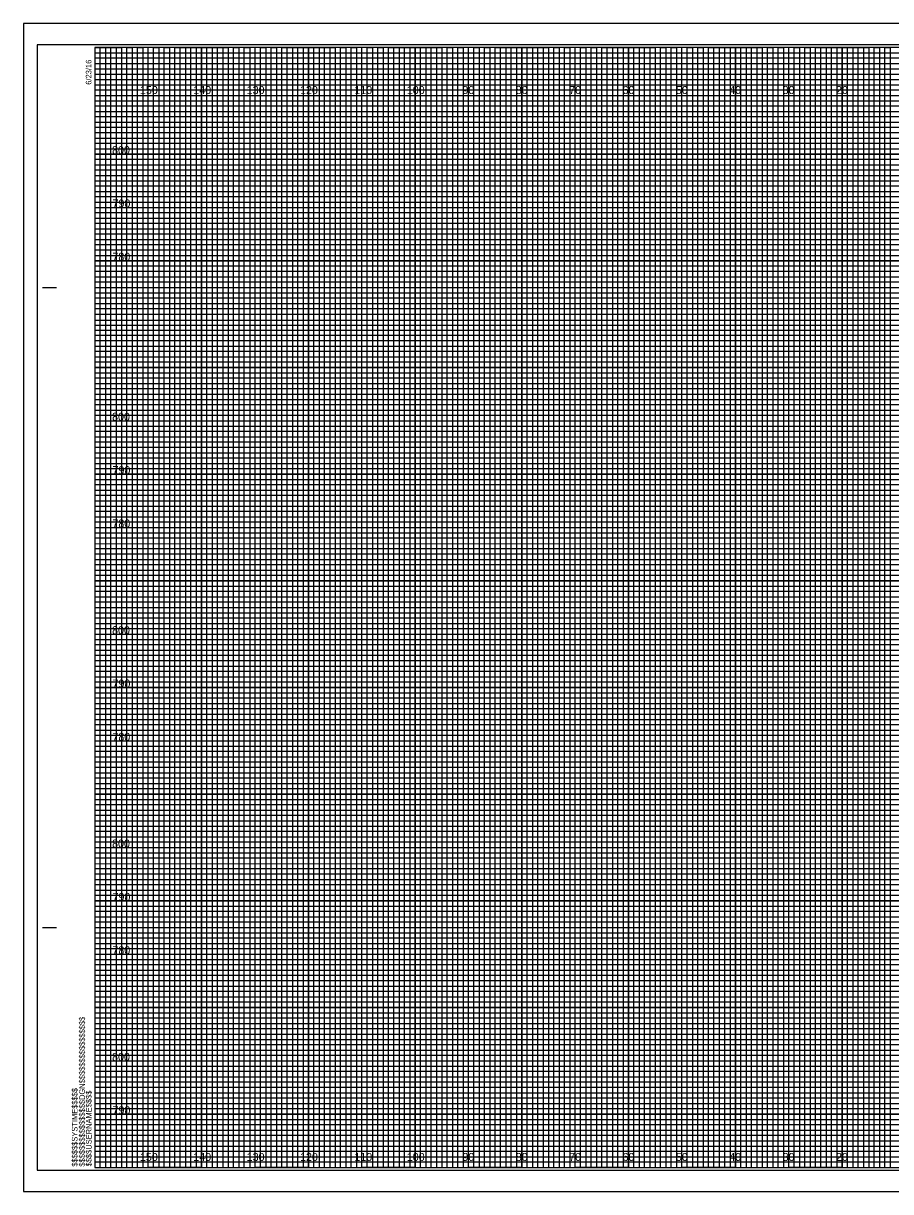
# Model space of a CAD drawing. Extents: x 9987 to 10323, y 9996 to 10214.
# Drawn here: x 9986.6 to 10149.1, y 9995.5 to 10214.5 of the extents above; entities that cross this region are included whole.
import ezdxf

# ---------------------------------------------------------------- set-up
doc = ezdxf.new("R2010")
doc.units = 0
for name, color, linetype in [('Exist Cross Section Cell', 7, 'Continuous'), ('Exist XS Center Line Elevation Label', 7, 'Continuous'), ('Exist XS Ground Line', 7, 'Continuous'), ('Prop CMT Conc Surface', 7, 'Continuous'), ('Prop CMT Concrete Structures', 7, 'Continuous'), ('Prop CMT Pvmt Course 1', 7, 'Continuous'), ('Prop CMT Pvmt Course 1 CG', 7, 'Continuous'), ('Prop CMT Pvmt Course 2', 7, 'Continuous'), ('Prop CMT Pvmt Course 3', 7, 'Continuous'), ('Prop CMT Pvmt Surface', 7, 'Continuous'), ('Prop XS Shear Point Element', 7, 'Continuous')]:
    doc.layers.add(name, color=color, linetype=linetype)

msp = doc.modelspace()

# ---------------------------------------------------------------- linework, layer by layer
at = {"layer": 'Exist XS Center Line Elevation Label'}
for points in [[(10000, 10210), (10005, 10210), (10005, 10000), (10015, 10000), (10015, 10210), (10025, 10210), (10025, 10000), (10035, 10000), (10035, 10210), (10045, 10210), (10045, 10000), (10055, 10000), (10055, 10210), (10065, 10210), (10065, 10000), (10075, 10000), (10075, 10210), (10085, 10210), (10085, 10000), (10095, 10000), (10095, 10210), (10105, 10210), (10105, 10000), (10115, 10000), (10115, 10210), (10125, 10210), (10125, 10000), (10135, 10000), (10135, 10210), (10145, 10210), (10145, 10000), (10155, 10000)], [(10000, 10205), (10275, 10205)], [(10000, 10185), (10320, 10185), (10320, 10195), (10000, 10195)], [(10000, 10165), (10320, 10165), (10320, 10175), (10000, 10175)], [(10000, 10145), (10320, 10145), (10320, 10155), (10000, 10155)], [(10000, 10125), (10320, 10125), (10320, 10135), (10000, 10135)], [(10000, 10105), (10320, 10105), (10320, 10115), (10000, 10115)], [(10000, 10085), (10320, 10085), (10320, 10095), (10000, 10095)], [(10000, 10065), (10320, 10065), (10320, 10075), (10000, 10075)], [(10000, 10045), (10320, 10045), (10320, 10055), (10000, 10055)], [(10000, 10025), (10320, 10025), (10320, 10035), (10000, 10035)], [(10000, 10005), (10320, 10005), (10320, 10015), (10000, 10015)]]:
    msp.add_lwpolyline(points, dxfattribs=at)
at = {"layer": 'Exist XS Ground Line'}
for p, q in [((10010, 10210), (10000, 10210)), ((10010, 10000), (10010, 10210)), ((10030, 10210), (10020, 10210)), ((10020, 10210), (10020, 10000)), ((10030, 10000), (10030, 10210)), ((10050, 10210), (10040, 10210)), ((10040, 10210), (10040, 10000)), ((10050, 10000), (10050, 10210)), ((10070, 10210), (10060, 10210)), ((10060, 10210), (10060, 10000)), ((10070, 10000), (10070, 10210)), ((10090, 10210), (10080, 10210)), ((10080, 10210), (10080, 10000)), ((10090, 10000), (10090, 10210)), ((10110, 10210), (10100, 10210)), ((10100, 10210), (10100, 10000)), ((10110, 10000), (10110, 10210)), ((10130, 10210), (10120, 10210)), ((10120, 10210), (10120, 10000)), ((10130, 10000), (10130, 10210)), ((10150, 10210), (10140, 10210)), ((10140, 10210), (10140, 10000)), ((10020, 10000), (10010, 10000)), ((10040, 10000), (10030, 10000)), ((10060, 10000), (10050, 10000)), ((10080, 10000), (10070, 10000)), ((10100, 10000), (10090, 10000)), ((10120, 10000), (10110, 10000)), ((10140, 10000), (10130, 10000))]:
    msp.add_line(p, q, dxfattribs=at)
for points in [[(10000, 10200), (10320, 10200), (10320, 10190), (10000, 10190)], [(10000, 10180), (10320, 10180), (10320, 10170), (10000, 10170)], [(10000, 10160), (10320, 10160), (10320, 10150), (10000, 10150)], [(10000, 10140), (10320, 10140), (10320, 10130), (10000, 10130)], [(10000, 10120), (10320, 10120), (10320, 10110), (10000, 10110)], [(10000, 10100), (10320, 10100), (10320, 10090), (10000, 10090)], [(10000, 10080), (10320, 10080), (10320, 10070), (10000, 10070)], [(10000, 10060), (10320, 10060), (10320, 10050), (10000, 10050)], [(10000, 10040), (10320, 10040), (10320, 10030), (10000, 10030)], [(10000, 10020), (10320, 10020), (10320, 10010), (10000, 10010)]]:
    msp.add_lwpolyline(points, dxfattribs=at)
at = {"layer": 'Prop CMT Conc Surface'}
for p, q in [((10323.3, 10214.5), (9986.6, 10214.5)), ((9986.6, 10214.5), (9986.6, 9995.5)), ((9986.6, 9995.5), (10323.3, 9995.5))]:
    msp.add_line(p, q, dxfattribs=at)
msp.add_lwpolyline([(9986.6, 9995.5), (10323.3, 9995.5), (10323.3, 10214.5), (9986.6, 10214.5)], close=True, dxfattribs=at)
at = {"layer": 'Prop CMT Concrete Structures'}
for points in [[(10000, 10000), (10001, 10000), (10001, 10210), (10002, 10210), (10002, 10000)], [(10002, 10000), (10003, 10000), (10003, 10210), (10004, 10210), (10004, 10000)], [(10005, 10000), (10006, 10000), (10006, 10210), (10007, 10210), (10007, 10000)], [(10007, 10000), (10008, 10000), (10008, 10210), (10009, 10210), (10009, 10000)], [(10010, 10000), (10011, 10000), (10011, 10210), (10012, 10210), (10012, 10000)], [(10012, 10000), (10013, 10000), (10013, 10210), (10014, 10210), (10014, 10000)], [(10015, 10000), (10016, 10000), (10016, 10210), (10017, 10210), (10017, 10000)], [(10017, 10000), (10018, 10000), (10018, 10210), (10019, 10210), (10019, 10000)], [(10020, 10000), (10021, 10000), (10021, 10210), (10022, 10210), (10022, 10000)], [(10022, 10000), (10023, 10000), (10023, 10210), (10024, 10210), (10024, 10000)], [(10025, 10000), (10026, 10000), (10026, 10210), (10027, 10210), (10027, 10000)], [(10027, 10000), (10028, 10000), (10028, 10210), (10029, 10210), (10029, 10000)], [(10030, 10000), (10031, 10000), (10031, 10210), (10032, 10210), (10032, 10000)], [(10032, 10000), (10033, 10000), (10033, 10210), (10034, 10210), (10034, 10000)], [(10035, 10000), (10036, 10000), (10036, 10210), (10037, 10210), (10037, 10000)], [(10037, 10000), (10038, 10000), (10038, 10210), (10039, 10210), (10039, 10000)], [(10040, 10000), (10041, 10000), (10041, 10210), (10042, 10210), (10042, 10000)], [(10042, 10000), (10043, 10000), (10043, 10210), (10044, 10210), (10044, 10000)], [(10045, 10000), (10046, 10000), (10046, 10210), (10047, 10210), (10047, 10000)], [(10047, 10000), (10048, 10000), (10048, 10210), (10049, 10210), (10049, 10000)], [(10050, 10000), (10051, 10000), (10051, 10210), (10052, 10210), (10052, 10000)], [(10052, 10000), (10053, 10000), (10053, 10210), (10054, 10210), (10054, 10000)], [(10055, 10000), (10056, 10000), (10056, 10210), (10057, 10210), (10057, 10000)], [(10057, 10000), (10058, 10000), (10058, 10210), (10059, 10210), (10059, 10000)], [(10060, 10000), (10061, 10000), (10061, 10210), (10062, 10210), (10062, 10000)], [(10062, 10000), (10063, 10000), (10063, 10210), (10064, 10210), (10064, 10000)], [(10065, 10000), (10066, 10000), (10066, 10210), (10067, 10210), (10067, 10000)], [(10067, 10000), (10068, 10000), (10068, 10210), (10069, 10210), (10069, 10000)], [(10070, 10000), (10071, 10000), (10071, 10210), (10072, 10210), (10072, 10000)], [(10072, 10000), (10073, 10000), (10073, 10210), (10074, 10210), (10074, 10000)], [(10075, 10000), (10076, 10000), (10076, 10210), (10077, 10210), (10077, 10000)], [(10077, 10000), (10078, 10000), (10078, 10210), (10079, 10210), (10079, 10000)], [(10080, 10000), (10081, 10000), (10081, 10210), (10082, 10210), (10082, 10000)], [(10082, 10000), (10083, 10000), (10083, 10210), (10084, 10210), (10084, 10000)], [(10085, 10000), (10086, 10000), (10086, 10210), (10087, 10210), (10087, 10000)], [(10087, 10000), (10088, 10000), (10088, 10210), (10089, 10210), (10089, 10000)], [(10090, 10000), (10091, 10000), (10091, 10210), (10092, 10210), (10092, 10000)], [(10092, 10000), (10093, 10000), (10093, 10210), (10094, 10210), (10094, 10000)], [(10095, 10000), (10096, 10000), (10096, 10210), (10097, 10210), (10097, 10000)], [(10097, 10000), (10098, 10000), (10098, 10210), (10099, 10210), (10099, 10000)], [(10100, 10000), (10101, 10000), (10101, 10210), (10102, 10210), (10102, 10000)], [(10102, 10000), (10103, 10000), (10103, 10210), (10104, 10210), (10104, 10000)], [(10105, 10000), (10106, 10000), (10106, 10210), (10107, 10210), (10107, 10000)], [(10107, 10000), (10108, 10000), (10108, 10210), (10109, 10210), (10109, 10000)], [(10110, 10000), (10111, 10000), (10111, 10210), (10112, 10210), (10112, 10000)], [(10112, 10000), (10113, 10000), (10113, 10210), (10114, 10210), (10114, 10000)], [(10115, 10000), (10116, 10000), (10116, 10210), (10117, 10210), (10117, 10000)], [(10117, 10000), (10118, 10000), (10118, 10210), (10119, 10210), (10119, 10000)], [(10120, 10000), (10121, 10000), (10121, 10210), (10122, 10210), (10122, 10000)], [(10122, 10000), (10123, 10000), (10123, 10210), (10124, 10210), (10124, 10000)], [(10125, 10000), (10126, 10000), (10126, 10210), (10127, 10210), (10127, 10000)], [(10127, 10000), (10128, 10000), (10128, 10210), (10129, 10210), (10129, 10000)], [(10130, 10000), (10131, 10000), (10131, 10210), (10132, 10210), (10132, 10000)], [(10132, 10000), (10133, 10000), (10133, 10210), (10134, 10210), (10134, 10000)], [(10135, 10000), (10136, 10000), (10136, 10210), (10137, 10210), (10137, 10000)], [(10137, 10000), (10138, 10000), (10138, 10210), (10139, 10210), (10139, 10000)], [(10140, 10000), (10141, 10000), (10141, 10210), (10142, 10210), (10142, 10000)], [(10142, 10000), (10143, 10000), (10143, 10210), (10144, 10210), (10144, 10000)], [(10145, 10000), (10146, 10000), (10146, 10210), (10147, 10210), (10147, 10000)], [(10147, 10000), (10148, 10000), (10148, 10210), (10149, 10210), (10149, 10000)]]:
    msp.add_lwpolyline(points, dxfattribs=at)
at = {"layer": 'Prop CMT Pvmt Course 1'}
msp.add_lwpolyline([(9989.2, 9999.5), (10322.4, 9999.5), (10322.4, 10210.5), (9989.2, 10210.5)], close=True, dxfattribs=at)
at = {"layer": 'Prop CMT Pvmt Course 1 CG'}
msp.add_lwpolyline([(9986.6, 9995.5), (10323.3, 9995.5), (10323.3, 10214.5), (9986.6, 10214.5)], close=True, dxfattribs=at)
at = {"layer": 'Prop CMT Pvmt Course 2'}
for p, q in [((10000, 10209), (10260, 10209)), ((10260, 10207.98), (10000, 10207.98)), ((10000, 10207.98), (10000, 10207)), ((10000, 10207), (10260, 10207)), ((10260, 10205.89), (10000, 10205.89)), ((10000, 10205.89), (10000, 10204)), ((10000, 10204), (10320, 10204))]:
    msp.add_line(p, q, dxfattribs=at)
for points in [[(10000, 10203), (10270, 10203), (10320, 10203), (10320, 10202), (10000, 10202)], [(10000, 10201), (10320, 10201), (10320, 10199), (10000, 10199)], [(10000, 10198), (10320, 10198), (10320, 10197), (10000, 10196.98)], [(10000, 10196), (10320, 10196), (10320, 10194), (10000, 10194)], [(10000, 10193), (10320, 10193), (10320, 10192), (10000, 10192)], [(10000, 10191), (10320, 10191), (10320, 10189), (10000, 10189)], [(10000, 10188), (10320, 10188), (10320, 10187), (10000, 10187)], [(10000, 10186), (10320, 10186), (10320, 10184), (10000, 10184)], [(10000, 10183), (10320, 10183), (10320, 10182), (10000, 10182)], [(10000, 10181), (10320, 10181), (10320, 10179), (10000, 10179)], [(10000, 10178), (10320, 10178), (10320, 10177), (10000, 10177)], [(10000, 10176), (10320, 10176), (10320, 10173.95), (10320, 10173), (10320, 10172), (10000, 10172)], [(10000, 10174), (10320, 10174), (10320, 10173), (10000, 10173)], [(10000, 10171), (10320, 10171), (10320, 10169), (10000, 10169.03)], [(10000, 10169.03), (10320, 10169), (10320, 10168), (10000, 10168)], [(10000, 10167), (10320, 10167), (10320, 10166), (10000, 10166)], [(10000, 10164), (10320, 10164), (10320, 10163), (10000, 10163)], [(10000, 10162), (10320, 10162), (10320, 10161), (10000, 10161)], [(9999.93, 10158.89), (10320, 10158.89), (10320, 10157.88), (9999.93, 10157.88)], [(10000, 10157), (10320, 10157), (10320, 10156), (10000, 10156)], [(10000, 10154), (10320, 10154), (10320, 10153), (10000, 10153)], [(10000, 10152), (10320, 10152), (10320, 10151), (10000, 10151)], [(10000, 10149), (10320, 10149), (10320, 10148), (10000, 10148)], [(10000, 10147), (10320, 10147), (10320, 10146), (10000, 10146)], [(10000, 10144), (10320, 10144), (10320, 10143), (10000, 10143)], [(10000, 10142), (10320, 10142), (10320, 10141), (10000, 10141)], [(10000, 10139), (10320, 10139), (10319.99, 10137.98), (10000, 10138)], [(10000, 10137), (10320, 10137), (10320, 10136), (10000, 10136)], [(10000, 10134), (10320, 10134), (10320, 10133), (10000, 10133)], [(10000, 10132), (10320, 10132), (10320, 10131), (10000, 10131)], [(10000, 10129), (10320, 10129), (10320, 10128), (10000, 10128)], [(10000, 10127), (10320, 10127), (10320, 10126), (10000, 10126)], [(10000, 10124), (10320, 10124), (10320, 10123), (10000, 10123)], [(10000, 10122), (10320, 10122), (10320, 10121), (10000, 10121)], [(10000, 10119), (10320, 10119), (10320, 10118), (10000, 10118)], [(10000, 10116.99), (10320.07, 10116.91), (10320, 10116), (10000, 10116)], [(10000, 10114), (10320, 10114), (10320, 10113), (10000, 10113)], [(10000, 10112), (10320, 10112), (10320, 10111), (10000, 10111)], [(10000, 10109), (10320, 10109), (10320, 10108), (10000, 10108)], [(10000, 10107), (10320, 10107), (10320, 10106), (10000, 10106)], [(10000, 10104), (10320, 10104), (10320, 10103), (10000, 10103)], [(10000, 10102), (10320, 10102), (10320, 10101), (10000, 10101)], [(10000, 10099), (10320, 10099), (10320, 10098), (10000, 10098)], [(10000, 10097), (10320, 10097), (10320, 10096), (10000, 10096)], [(10000, 10094), (10320, 10094), (10320, 10093), (10000, 10093)], [(10000, 10092), (10320, 10092), (10320, 10091), (10000, 10091)], [(10000, 10089), (10320, 10089), (10320, 10088), (10000, 10088)], [(10000, 10087), (10320, 10087), (10320, 10086), (10000, 10086)], [(10000, 10084), (10320, 10084), (10320, 10083), (10000, 10083)], [(10000, 10082), (10320, 10082), (10320, 10081), (10000, 10081)], [(10000, 10079), (10320, 10079), (10319.99, 10077.98), (10000, 10078)], [(10000, 10077), (10320, 10077), (10320, 10076), (10000, 10076)], [(10000, 10074), (10320, 10074), (10320, 10073), (10000, 10073)], [(10000, 10072), (10320, 10072), (10320, 10071), (10000, 10071)], [(10000, 10069), (10320, 10069), (10320, 10068), (10000, 10068)], [(10000, 10067), (10320, 10067), (10320, 10066), (10000, 10066)], [(10000, 10064), (10320, 10064), (10320, 10063), (10000, 10063)], [(10000, 10062), (10320, 10062), (10320, 10061), (10000, 10061)], [(10000, 10059), (10320, 10059), (10320, 10058), (10000, 10058)], [(10000, 10056.99), (10320.07, 10056.91), (10320, 10056), (10000, 10056)], [(10000, 10054), (10320, 10054), (10320, 10053), (10000, 10053)], [(10000, 10052), (10320, 10052), (10320, 10051), (10000, 10051)], [(10000, 10049), (10320, 10049), (10320, 10048), (10000, 10048)], [(10000, 10047), (10320, 10047), (10320, 10046), (10000, 10046)], [(10000, 10044), (10320, 10044), (10320, 10043), (10000, 10043)], [(10000, 10042), (10320, 10042), (10320, 10041), (10000, 10041)], [(10000, 10039), (10320, 10039), (10320, 10038), (10000, 10038)], [(10000, 10037), (10320, 10037), (10320, 10036), (10000, 10036)], [(10000, 10034), (10320, 10034), (10320, 10033), (10000, 10033)], [(10000, 10032), (10320, 10032), (10320, 10031), (10000, 10031)], [(10000, 10029), (10320, 10029), (10320, 10028), (10000, 10028)], [(10000, 10027), (10320, 10027), (10320, 10026), (10000, 10026)], [(10000, 10024), (10320, 10024), (10320, 10023), (10000, 10023)], [(10000, 10022), (10320, 10022), (10320, 10021), (10000, 10021)], [(10000, 10019), (10320, 10019), (10320, 10018), (10000, 10018)], [(10000, 10017), (10320, 10017), (10320, 10016), (10000, 10016)], [(10000, 10014), (10320, 10014), (10320, 10013), (10000, 10013)], [(10000, 10012), (10320, 10012), (10320, 10011), (10000, 10011)], [(10000, 10009), (10320, 10009), (10320, 10008), (10000, 10008)], [(10000, 10007), (10320, 10007), (10320, 10006), (10000, 10006)], [(10000, 10004), (10320, 10004), (10320, 10003), (10000, 10003)], [(10000, 10002), (10320, 10002), (10320, 10001), (10000, 10001)]]:
    msp.add_lwpolyline(points, dxfattribs=at)
at = {"layer": 'Prop CMT Pvmt Course 3'}
for p, q in [((9990.2, 10165), (9992.7, 10165)), ((9990.3, 10165), (9992.8, 10165)), ((9990.2, 10045), (9992.7, 10045)), ((9990.3, 10045), (9992.8, 10045)), ((10000, 10000), (10000, 10000)), ((10000, 10000), (10000, 10000)), ((10000, 10000), (10000, 10000)), ((10000, 10000), (10000, 10000)), ((10000, 10000), (10000, 10000)), ((10000, 10000), (10000, 10000)), ((10000, 10000), (10000, 10000))]:
    msp.add_line(p, q, dxfattribs=at)
msp.add_lwpolyline([(10320, 10210), (10000, 10210), (10000, 10000), (10320, 10000)], close=True, dxfattribs=at)
at = {"layer": 'Prop XS Shear Point Element'}
for p, q in [((10010, 10000), (10010, 10210)), ((10020, 10000), (10020, 10210)), ((10030, 10000), (10030, 10210)), ((10040, 10000), (10040, 10210)), ((10050, 10000), (10050, 10210)), ((10060, 10000), (10060, 10210)), ((10070, 10000), (10070, 10210)), ((10080, 10000), (10080, 10210)), ((10090, 10000), (10090, 10210)), ((10100, 10000), (10100, 10210)), ((10110, 10000), (10110, 10210)), ((10120, 10000), (10120, 10210)), ((10130, 10000), (10130, 10210)), ((10140, 10000), (10140, 10210)), ((10000, 10200), (10320, 10200)), ((10000, 10190), (10320, 10190)), ((10000, 10180), (10320, 10180)), ((10000, 10170), (10320, 10170)), ((10000, 10160), (10320, 10160)), ((10000, 10150), (10320, 10150)), ((10000, 10140), (10320, 10140)), ((10000, 10130), (10320, 10130)), ((10000, 10120), (10320, 10120)), ((10000, 10110), (10320, 10110)), ((10000, 10100), (10320, 10100)), ((10000, 10090), (10320, 10090)), ((10000, 10080), (10320, 10080)), ((10000, 10070), (10320, 10070)), ((10000, 10060), (10320, 10060)), ((10000, 10050), (10320, 10050)), ((10000, 10040), (10320, 10040)), ((10000, 10030), (10320, 10030)), ((10000, 10020), (10320, 10020)), ((10000, 10010), (10320, 10010))]:
    msp.add_line(p, q, dxfattribs=at)

# ---------------------------------------------------------------- texts
at = {"layer": 'Exist Cross Section Cell'}
for s, p in [('150', (10008.44, 10201.25)), ('140', (10018.44, 10201.25)), ('130', (10028.44, 10201.25)), ('120', (10038.44, 10201.25)), ('110', (10048.62, 10201.25)), ('100', (10058.44, 10201.25)), ('90', (10068.86, 10201.25)), ('80', (10078.86, 10201.25)), ('70', (10088.86, 10201.25)), ('60', (10098.86, 10201.25)), ('50', (10108.86, 10201.25)), ('40', (10118.86, 10201.25)), ('30', (10128.86, 10201.25)), ('20', (10138.86, 10201.25)), ('150', (10008.44, 10001.25)), ('140', (10018.44, 10001.25)), ('130', (10028.44, 10001.25)), ('120', (10038.44, 10001.25)), ('110', (10048.62, 10001.25)), ('100', (10058.44, 10001.25)), ('90', (10068.86, 10001.25)), ('80', (10078.86, 10001.25)), ('70', (10088.86, 10001.25)), ('60', (10098.86, 10001.25)), ('50', (10108.86, 10001.25)), ('40', (10118.86, 10001.25)), ('30', (10128.86, 10001.25)), ('20', (10138.86, 10001.25))]:
    msp.add_text(s, height=1.5, dxfattribs=at).set_placement(p)
at = {"layer": 'Prop CMT Pvmt Course 3'}
for s, p in [('6/23/16', (9999.35, 10203)), ('$$$$$$$$$$$$$$$$DGN$$$$$$$$$$$$$$$$', (9998.12, 10000.18)), ('$$$$$$SYSTIME$$$$$', (9996.74, 10000.18)), ('$$$$USERNAME$$$$', (9999.38, 10000.23))]:
    msp.add_text(s, height=1.05, rotation=90, dxfattribs=at).set_placement(p)
at = {"layer": 'Prop CMT Pvmt Surface'}
for s, p in [('800', (10003.22, 10190)), ('790', (10003.3, 10180)), ('780', (10003.28, 10170)), ('800', (10003.22, 10140)), ('790', (10003.3, 10130)), ('780', (10003.28, 10120)), ('800', (10003.22, 10100)), ('790', (10003.3, 10090)), ('780', (10003.28, 10080)), ('800', (10003.22, 10060)), ('790', (10003.3, 10050)), ('780', (10003.28, 10040)), ('800', (10003.22, 10020)), ('790', (10003.3, 10010))]:
    msp.add_text(s, height=1.5, dxfattribs=at).set_placement(p)

doc.saveas('drawing.dxf')
